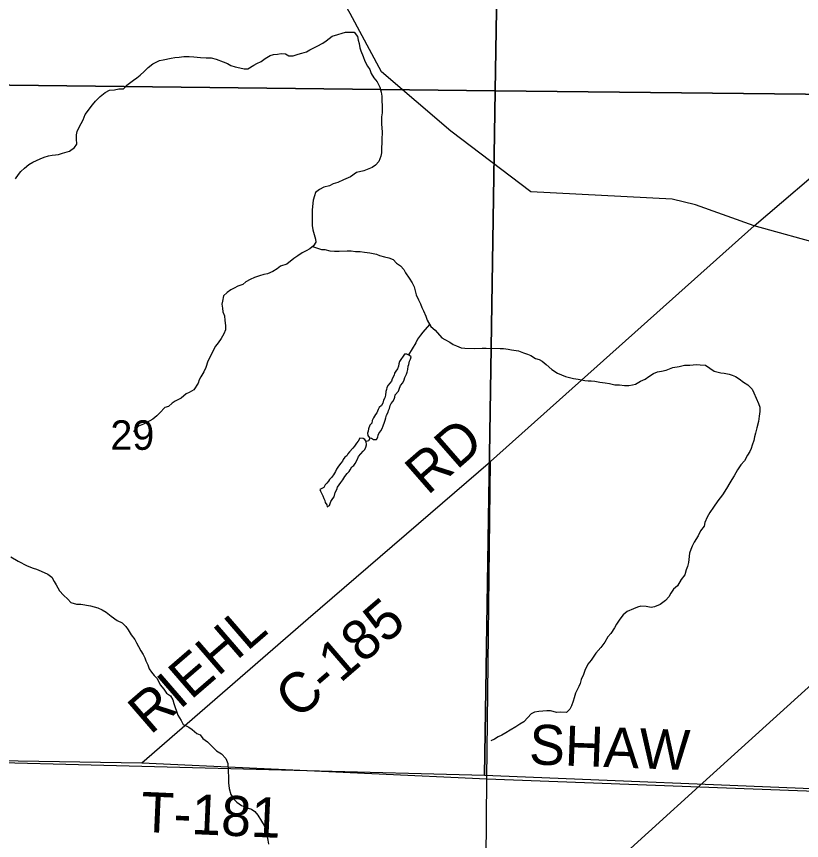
# Model space of a CAD drawing. Extents: x 36.7 to 70.7, y 0 to 22.
# Drawn here: x 42.544 to 43.658, y 14.842 to 16.011 of the extents above; entities that cross this region are included whole.
import ezdxf

# ---------------------------------------------------------------- set-up
doc = ezdxf.new("R2010")
doc.units = 0
for name, color, linetype in [('GM_X_County_Road', 7, 'Continuous'), ('GM_X_County_Road_Text', 7, 'Continuous'), ('GM_X_Minor_Lake', 7, 'Continuous'), ('GM_X_Minor_River', 7, 'Continuous'), ('GM_X_Rail_Line', 7, 'Continuous'), ('GM_X_Section', 7, 'Continuous'), ('GM_X_Section_Text', 7, 'Continuous'), ('GM_X_Township_Road', 7, 'Continuous'), ('GM_X_Township_Road_Text', 7, 'Continuous')]:
    doc.layers.add(name, color=color, linetype=linetype)

msp = doc.modelspace()

# ---------------------------------------------------------------- linework, layer by layer
at = {"layer": 'GM_X_County_Road'}
msp.add_line((42.202, 14.9604), (42.7218, 14.9518), dxfattribs=at)
msp.add_lwpolyline([(42.7218, 14.9518), (42.9578, 15.1566), (43.2165, 15.3796), (43.5905, 15.714), (43.7102, 15.8162), (43.9134, 15.9918), (43.977, 16.0478)], dxfattribs=at)
at = {"layer": 'GM_X_Minor_Lake'}
for points in [[(43.0945, 15.5317), (43.0875, 15.5216), (43.0863, 15.5182), (43.0858, 15.5148), (43.0846, 15.5111), (43.0819, 15.5077), (43.0803, 15.5047), (43.0799, 15.5021), (43.0768, 15.4968), (43.0759, 15.4934), (43.0713, 15.4878), (43.0693, 15.4844), (43.0689, 15.4818), (43.0681, 15.4788), (43.0672, 15.4735), (43.0664, 15.4697), (43.0644, 15.4663), (43.0635, 15.4622), (43.0616, 15.4592), (43.0585, 15.4562), (43.0569, 15.4532), (43.0553, 15.4487), (43.053, 15.4461), (43.0506, 15.4416), (43.0487, 15.4378), (43.0478, 15.4337), (43.0451, 15.4311), (43.0435, 15.4258), (43.0427, 15.4224), (43.0418, 15.4197), (43.0422, 15.4163), (43.0447, 15.4132), (43.0456, 15.413)], [(43.0456, 15.413), (43.0474, 15.4124), (43.0504, 15.4105), (43.0545, 15.4108), (43.0565, 15.4141), (43.0569, 15.4168), (43.0581, 15.4194), (43.0608, 15.4232), (43.0628, 15.4265), (43.064, 15.4299), (43.066, 15.4352), (43.0668, 15.4382), (43.068, 15.4416), (43.0689, 15.4454), (43.0712, 15.4495), (43.0717, 15.4521), (43.0732, 15.4548), (43.0741, 15.4589), (43.0756, 15.4616), (43.078, 15.4645), (43.0796, 15.4679), (43.0808, 15.4706), (43.0812, 15.4743), (43.0859, 15.4792), (43.0867, 15.4822), (43.0887, 15.4875), (43.0918, 15.4912), (43.0941, 15.4953), (43.095, 15.4987), (43.097, 15.5036), (43.0982, 15.5062), (43.099, 15.51), (43.0998, 15.5146), (43.1003, 15.5172), (43.1015, 15.5217), (43.1031, 15.5247), (43.1039, 15.5278), (43.1013, 15.5301), (43.0979, 15.5317), (43.0945, 15.5317)], [(43.0311, 15.4124), (43.0284, 15.4086), (43.0264, 15.4053), (43.0233, 15.4011), (43.0213, 15.3985), (43.0163, 15.3933), (43.014, 15.3903), (43.0124, 15.3877), (43.0097, 15.3855), (43.0074, 15.3825), (43.0062, 15.3799), (43.0039, 15.3772), (43.0007, 15.3728), (42.998, 15.3686), (42.9964, 15.3653), (42.9937, 15.3604), (42.9906, 15.3566), (42.9879, 15.354), (42.9867, 15.3514), (42.9843, 15.3488), (42.9816, 15.3466), (42.9797, 15.3425), (42.9743, 15.3399), (42.975, 15.3372), (42.9765, 15.3345), (42.9783, 15.3307), (42.9801, 15.3269), (42.9812, 15.3242), (42.9819, 15.3215), (42.9841, 15.3181), (42.9848, 15.3154), (42.9878, 15.3169), (42.9887, 15.3199), (42.9899, 15.3229), (42.9926, 15.327), (42.9945, 15.3296), (42.9962, 15.3357), (42.9982, 15.3398), (42.9994, 15.3432), (43.0041, 15.3499), (43.0068, 15.3533), (43.0099, 15.3582), (43.013, 15.3623), (43.0157, 15.3653), (43.0173, 15.3679), (43.0197, 15.372), (43.0223, 15.3738), (43.0243, 15.3765), (43.0275, 15.3828), (43.029, 15.3866), (43.0356, 15.3941), (43.038, 15.3967), (43.0395, 15.3997), (43.0404, 15.4031), (43.04, 15.4079)], [(43.04, 15.4079), (43.0383, 15.4107), (43.0356, 15.4123), (43.0311, 15.4124)]]:
    msp.add_lwpolyline(points, dxfattribs=at)
at = {"layer": 'GM_X_Minor_River'}
for points in [[(42.5425, 15.7805), (42.5468, 15.7865), (42.5502, 15.791), (42.5552, 15.7959), (42.5613, 15.8008), (42.5671, 15.8041), (42.5724, 15.8067), (42.5774, 15.8089), (42.5831, 15.8115), (42.5895, 15.8134), (42.5945, 15.8141), (42.599, 15.8148), (42.6036, 15.8151), (42.6093, 15.8169), (42.6192, 15.8199), (42.6261, 15.8251), (42.6296, 15.8296), (42.6289, 15.8372), (42.629, 15.8429), (42.6298, 15.8475), (42.6321, 15.8531), (42.6356, 15.8592), (42.6383, 15.8641), (42.6414, 15.872), (42.6518, 15.8856), (42.6561, 15.8908), (42.6626, 15.8972), (42.6699, 15.9032), (42.676, 15.9062), (42.6828, 15.9069), (42.6889, 15.908), (42.6957, 15.9083), (42.7003, 15.9132), (42.7099, 15.9203), (42.7148, 15.924), (42.7194, 15.9274), (42.7248, 15.933), (42.7306, 15.9386), (42.7371, 15.9435), (42.742, 15.9461), (42.7466, 15.9483), (42.7519, 15.9494), (42.7633, 15.9516), (42.7687, 15.9527), (42.7747, 15.9533), (42.7812, 15.954), (42.7888, 15.9543), (42.7956, 15.9535), (42.8051, 15.9526), (42.813, 15.9522), (42.8199, 15.9521), (42.8274, 15.9505), (42.8369, 15.9466), (42.8433, 15.9443), (42.8482, 15.9412), (42.8542, 15.9392), (42.8607, 15.938), (42.8667, 15.9364), (42.872, 15.9364), (42.8804, 15.942), (42.885, 15.9442), (42.8911, 15.9468), (42.8969, 15.9513), (42.9037, 15.9554), (42.9087, 15.9568), (42.914, 15.9575), (42.9193, 15.9583), (42.9254, 15.9578), (42.9303, 15.9551), (42.9363, 15.955), (42.9436, 15.9572), (42.9485, 15.9587), (42.9554, 15.9609), (42.96, 15.9635), (42.9657, 15.9665), (42.9703, 15.9687), (42.9783, 15.9728), (42.9832, 15.9765), (42.9917, 15.9829), (43, 15.9851), (43.0061, 15.9873), (43.0107, 15.9888), (43.0228, 15.9886), (43.0277, 15.9825), (43.0284, 15.9772), (43.0299, 15.9726), (43.0309, 15.9665), (43.0324, 15.962), (43.0357, 15.9543), (43.0383, 15.9475), (43.042, 15.9402), (43.045, 15.9356), (43.0472, 15.9299), (43.0509, 15.9238), (43.0558, 15.9181)], [(43.0558, 15.9181), (43.0595, 15.9108), (43.0613, 15.9036), (43.0624, 15.8979), (43.0623, 15.8903), (43.0626, 15.885), (43.0629, 15.88), (43.0625, 15.8743), (43.0617, 15.8683), (43.0616, 15.863), (43.0619, 15.8584), (43.0622, 15.8523), (43.0626, 15.8474), (43.0624, 15.836), (43.0624, 15.8314), (43.0619, 15.8246), (43.0615, 15.8174), (43.061, 15.8125), (43.0579, 15.8053), (43.0533, 15.7997), (43.0483, 15.7967), (43.0369, 15.7919), (43.0262, 15.7893), (43.0178, 15.7833), (43.0079, 15.7789), (42.9999, 15.7755), (42.9931, 15.7733), (42.9881, 15.7707), (42.9797, 15.7686), (42.974, 15.7656), (42.9683, 15.7611), (42.9667, 15.7565), (42.9647, 15.7505), (42.9634, 15.7365), (42.9633, 15.7285), (42.9636, 15.7209), (42.9636, 15.7144), (42.9643, 15.708), (42.9679, 15.695), (42.9686, 15.6905), (42.9651, 15.6856), (42.9602, 15.6811), (42.9548, 15.6785), (42.9491, 15.6755), (42.943, 15.6714), (42.9372, 15.6673), (42.9273, 15.6594), (42.9185, 15.6565), (42.9136, 15.6527), (42.9078, 15.649), (42.8998, 15.6457), (42.8949, 15.6446), (42.8888, 15.6431), (42.8816, 15.6405), (42.8755, 15.6379), (42.8693, 15.6346), (42.8648, 15.6308), (42.8579, 15.6283), (42.8526, 15.6253), (42.848, 15.6231), (42.8426, 15.6193), (42.8376, 15.6144), (42.836, 15.6072), (42.8352, 15.6027), (42.8363, 15.597), (42.8366, 15.592), (42.8388, 15.5863), (42.8395, 15.5795), (42.8406, 15.5723), (42.8405, 15.5662), (42.8382, 15.5605), (42.8343, 15.5541), (42.83, 15.5477), (42.8262, 15.5432), (42.8231, 15.5368), (42.8181, 15.5273), (42.8153, 15.5217), (42.8126, 15.513), (42.8095, 15.5065), (42.8056, 15.4998), (42.8029, 15.4952), (42.8017, 15.4907), (42.7955, 15.4813), (42.789, 15.4775), (42.7845, 15.4753), (42.7776, 15.4693), (42.7692, 15.4652), (42.7646, 15.4622), (42.7596, 15.4577), (42.7543, 15.4559), (42.7474, 15.4488), (42.7428, 15.4442), (42.7374, 15.4394), (42.729, 15.4349), (42.724, 15.4323), (42.7172, 15.4297), (42.7126, 15.426), (42.7099, 15.4214)], [(42.9639, 15.6844), (42.9765, 15.6805), (42.9814, 15.6801), (42.9886, 15.6785), (42.995, 15.6777), (43.0018, 15.678), (43.0132, 15.6786), (43.0189, 15.6782), (43.025, 15.6773), (43.0314, 15.6776), (43.0375, 15.6764), (43.0454, 15.6756), (43.0545, 15.6736), (43.0591, 15.672), (43.0662, 15.6697), (43.0723, 15.6685), (43.0783, 15.6661), (43.0828, 15.6608), (43.0885, 15.6569), (43.0933, 15.6519), (43.0956, 15.6474), (43.1012, 15.6397), (43.1053, 15.6332), (43.1079, 15.6271), (43.1097, 15.6218), (43.1111, 15.6161), (43.1141, 15.6088), (43.1171, 15.6031), (43.1189, 15.5981), (43.1211, 15.5932), (43.1245, 15.5859), (43.1267, 15.5798), (43.1315, 15.571), (43.1379, 15.566), (43.1472, 15.5549), (43.1518, 15.5526), (43.1589, 15.5487), (43.1634, 15.5456), (43.168, 15.5437), (43.1748, 15.541), (43.1801, 15.5402), (43.1941, 15.54), (43.2047, 15.5403), (43.2104, 15.5402), (43.2301, 15.54), (43.2347, 15.5396), (43.2415, 15.5387), (43.2464, 15.5379), (43.2559, 15.5363), (43.2631, 15.5336), (43.2687, 15.532), (43.2736, 15.53), (43.28, 15.5258), (43.2853, 15.5242), (43.2899, 15.5219), (43.2955, 15.5173), (43.3034, 15.51), (43.3113, 15.505), (43.323, 15.4999), (43.3343, 15.4975), (43.3408, 15.4963), (43.3502, 15.4943), (43.3548, 15.4939), (43.3593, 15.4938), (43.3646, 15.4934), (43.3715, 15.4922), (43.379, 15.4909), (43.3851, 15.4901), (43.393, 15.4885), (43.3995, 15.4881), (43.4063, 15.4872), (43.4124, 15.4872), (43.4177, 15.4883), (43.4223, 15.4893), (43.4291, 15.4934), (43.4356, 15.4964), (43.441, 15.5002), (43.4475, 15.5046), (43.4532, 15.5069), (43.4589, 15.5079), (43.4657, 15.509), (43.4749, 15.5127), (43.484, 15.5145), (43.4916, 15.5163), (43.4992, 15.5162), (43.5037, 15.5166), (43.5087, 15.5169), (43.514, 15.5168), (43.5216, 15.5164), (43.5336, 15.5079), (43.5431, 15.5055), (43.548, 15.5047), (43.5548, 15.5035), (43.5593, 15.5019), (43.5639, 15.5), (43.5691, 15.4969), (43.5755, 15.4923), (43.5816, 15.4884), (43.5876, 15.4823), (43.5902, 15.4769), (43.5935, 15.4693)], [(43.13, 15.5738), (43.1204, 15.5632), (43.1173, 15.5587), (43.1127, 15.553), (43.1104, 15.5481), (43.1, 15.5307)], [(43.5935, 15.4693), (43.5964, 15.462), (43.5983, 15.4567), (43.5986, 15.4506), (43.5977, 15.4438), (43.5965, 15.4362), (43.5941, 15.4275), (43.5922, 15.4196), (43.591, 15.4146), (43.5898, 15.4093), (43.5874, 15.4029), (43.5862, 15.398), (43.5843, 15.3935), (43.5808, 15.3886), (43.5769, 15.3803), (43.5715, 15.375), (43.5669, 15.3675), (43.5619, 15.3592), (43.5588, 15.3539), (43.5561, 15.3493), (43.5511, 15.341), (43.5453, 15.332), (43.5391, 15.3237), (43.5329, 15.3147), (43.5275, 15.3071), (43.524, 15.3007), (43.5205, 15.2932), (43.5197, 15.2879), (43.5143, 15.2811), (43.5108, 15.2739), (43.5054, 15.2649), (43.5027, 15.2592), (43.5008, 15.2547), (43.4988, 15.2494), (43.4976, 15.2406), (43.4971, 15.2361), (43.4959, 15.2304), (43.494, 15.2259), (43.492, 15.2187), (43.487, 15.2119), (43.4816, 15.2032), (43.4762, 15.1984), (43.4724, 15.1927), (43.4693, 15.1874), (43.4647, 15.1822), (43.457, 15.1765), (43.449, 15.1732), (43.4444, 15.1725), (43.4373, 15.1737), (43.4297, 15.1742), (43.4247, 15.1731), (43.4194, 15.1705), (43.4102, 15.1668), (43.4045, 15.1619), (43.3999, 15.1559), (43.3952, 15.1487), (43.3925, 15.1434), (43.3871, 15.1355), (43.3829, 15.1306), (43.3786, 15.1231), (43.3729, 15.1156), (43.3659, 15.1077), (43.3594, 15.0979), (43.3544, 15.0919), (43.3501, 15.0832), (43.3482, 15.0775), (43.345, 15.0703), (43.3435, 15.0646), (43.3415, 15.0601), (43.3372, 15.0507), (43.3353, 15.0442), (43.3337, 15.0393), (43.3313, 15.0329), (43.329, 15.028), (43.324, 15.0235), (43.3153, 15.0239), (43.3107, 15.0236), (43.3017, 15.0256), (43.2964, 15.0257), (43.285, 15.025), (43.2789, 15.0239), (43.2743, 15.0217), (43.2693, 15.0165), (43.2639, 15.0104), (43.2582, 15.0071), (43.2521, 15.003), (43.2441, 14.9985), (43.238, 14.9944), (43.2326, 14.9914), (43.2273, 14.9888), (43.2219, 14.9855), (43.217, 14.9832)], [(43.0456, 15.413), (43.0431, 15.4087), (43.04, 15.4079)], [(42.5357, 15.2441), (42.5462, 15.2383), (42.559, 15.2314), (42.5677, 15.2282), (42.5723, 15.2267), (42.579, 15.2239), (42.5885, 15.2196), (42.5941, 15.2154), (42.5975, 15.2093), (42.6001, 15.2047), (42.6049, 15.1959), (42.6105, 15.1898), (42.6165, 15.184), (42.621, 15.1794), (42.629, 15.1771), (42.6354, 15.177), (42.649, 15.1746), (42.6543, 15.1734), (42.6592, 15.1718), (42.6653, 15.1691), (42.6709, 15.1656), (42.6781, 15.1602), (42.6867, 15.1541), (42.6939, 15.1506), (42.6988, 15.1452), (42.7025, 15.1406), (42.7066, 15.1337), (42.7118, 15.1272), (42.7141, 15.1223), (42.717, 15.1169), (42.7204, 15.1108), (42.7237, 15.1058), (42.726, 15.1012)], [(42.726, 15.1012), (42.7274, 15.0967), (42.7304, 15.091), (42.7322, 15.0856), (42.7356, 15.0806), (42.7393, 15.076), (42.7435, 15.0715), (42.7479, 15.0627), (42.7528, 15.0565), (42.7569, 15.0508), (42.7625, 15.0469), (42.7659, 15.0416), (42.7669, 15.0363), (42.7692, 15.0306), (42.771, 15.0252), (42.7728, 15.0195), (42.7773, 15.0119), (42.7803, 15.0065), (42.7882, 15.0026), (42.7931, 14.9995), (42.7998, 14.9934), (42.8044, 14.9918), (42.8081, 14.9865), (42.8149, 14.9819), (42.822, 14.9746), (42.8276, 14.9692), (42.8348, 14.9646), (42.8408, 14.9584), (42.8437, 14.9512), (42.844, 14.9402), (42.8447, 14.9318), (42.8449, 14.9238), (42.8456, 14.9158), (42.8482, 14.9071), (42.8523, 14.9006), (42.8564, 14.896), (42.8632, 14.8914), (42.8726, 14.8875), (42.8771, 14.8863), (42.882, 14.8828), (42.8861, 14.8778), (42.8914, 14.8694), (42.8951, 14.8629), (42.8977, 14.8576), (42.8988, 14.853), (42.8995, 14.8469), (42.9005, 14.8424), (42.9016, 14.8367)]]:
    msp.add_lwpolyline(points, dxfattribs=at)
at = {"layer": 'GM_X_Rail_Line'}
msp.add_lwpolyline([(42.5932, 14.0969), (42.6018, 14.1045), (42.9057, 14.3723), (43.2092, 14.6439), (43.5174, 14.9236), (43.8818, 15.2533), (44.2007, 15.5398), (44.9423, 16.2118), (45.4899, 16.7019), (45.5934, 16.801)], dxfattribs=at)
at = {"layer": 'GM_X_Section'}
for points in [[(43.2397, 16.908), (43.2232, 15.9056), (42.2098, 15.9172), (42.2388, 16.9146)], [(44.2493, 16.9097), (44.2362, 15.8944), (43.2232, 15.9056), (43.2397, 16.908)], [(43.2232, 15.9056), (43.2077, 14.934), (42.199, 14.9604), (42.2098, 15.9172)], [(44.2362, 15.8944), (44.2284, 14.8924), (43.2077, 14.934), (43.2232, 15.9056)]]:
    msp.add_lwpolyline(points, close=True, dxfattribs=at)
at = {"layer": 'GM_X_Township_Road'}
for p, q in [((43.2111, 14.9295), (43.2165, 15.3796)), ((43.2035, 14.0969), (43.2111, 14.9295))]:
    msp.add_line(p, q, dxfattribs=at)
for points in [[(44.2818, 15.3016), (44.1278, 15.4892), (44.0315, 15.5895), (44.0183, 15.5966), (44.0021, 15.6014), (43.9968, 15.603), (43.9915, 15.6057), (43.973, 15.6102), (43.8985, 15.6289), (43.5905, 15.714), (43.5074, 15.7438), (43.4741, 15.7516), (43.2738, 15.762), (43.1602, 15.8481), (43.0617, 15.9325), (43.0175, 16.0153), (42.9702, 16.0985), (42.9678, 16.1373), (42.9675, 16.211)], [(42.7218, 14.9518), (43.2111, 14.9295), (44.6722, 14.8746)]]:
    msp.add_lwpolyline(points, dxfattribs=at)

# ---------------------------------------------------------------- texts
at = {"layer": 'GM_X_County_Road_Text'}
for s, rotation, p in [('RD', 41.14, (43.1271, 15.3306)), ('C-185', 40.7203, (42.9424, 15.012)), ('RIEHL', 40.8551, (42.7338, 14.9907))]:
    msp.add_text(s, height=0.05682, rotation=rotation, dxfattribs=at).set_placement(p)
at = {"layer": 'GM_X_Section_Text'}
msp.add_text('29', height=0.04186, rotation=0, dxfattribs=at).set_placement((42.6771, 15.3961))
at = {"layer": 'GM_X_Township_Road_Text'}
for s, rotation, p in [('SHAW', 357.8965, (43.2705, 14.95)), ('T-181', 357.4736, (42.7195, 14.8542))]:
    msp.add_text(s, height=0.05682, rotation=rotation, dxfattribs=at).set_placement(p)

doc.saveas('drawing.dxf')
